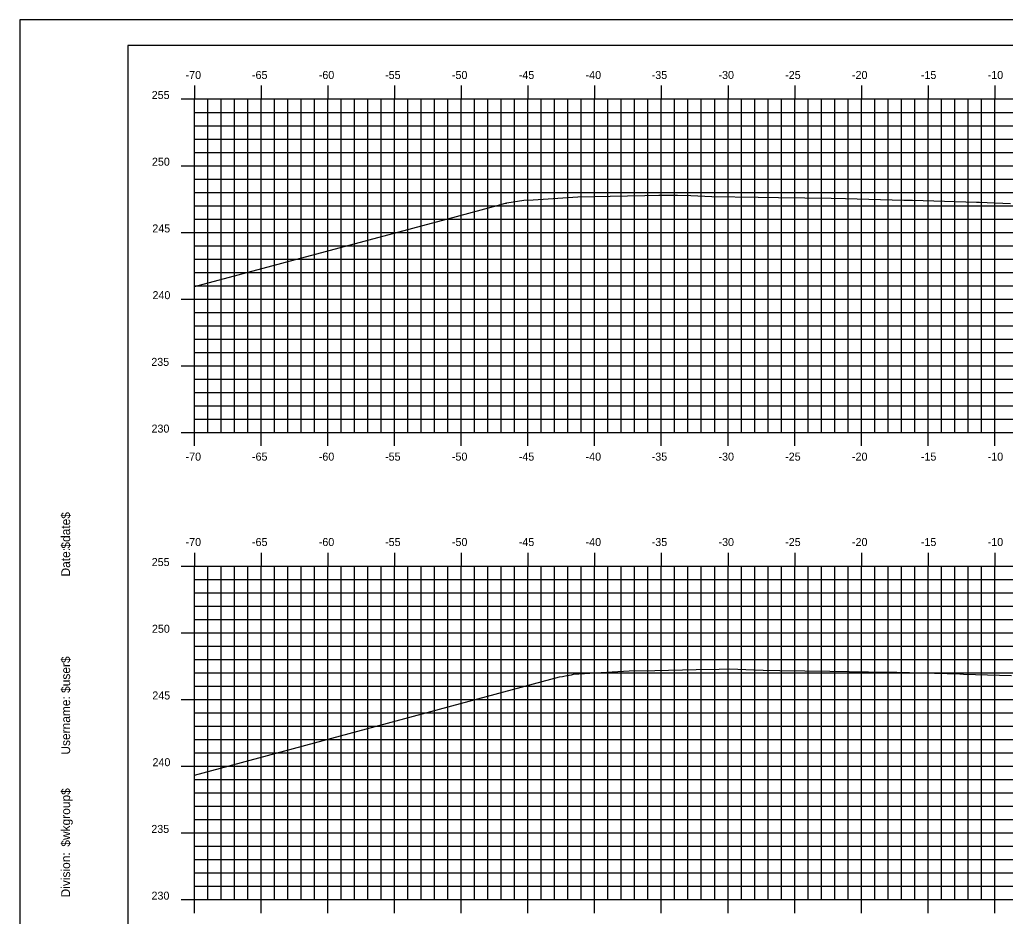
# Model space of a CAD drawing. Extents: x 1170543 to 1177585, y 609599 to 610623.
# Drawn here: x 1171725.9 to 1171799.7, y 609641.6 to 609708.8 of the extents above; entities that cross this region are included whole.
import ezdxf

# ---------------------------------------------------------------- set-up
doc = ezdxf.new("R2010")
doc.units = 0
for name, color, linetype in [('BORDER', 7, 'Continuous'), ('H_V ANNOTATION', 7, 'Continuous'), ('MAJOR', 7, 'Continuous'), ('MINOR', 7, 'Continuous'), ('PLOT BOUNDARY', 7, 'Continuous'), ('S_Roadway_Centerline', 7, 'Continuous')]:
    doc.layers.add(name, color=color, linetype=linetype)

msp = doc.modelspace()

# ---------------------------------------------------------------- linework, layer by layer
at = {"layer": 'BORDER'}
for p, q in [((1171893.965, 609706.872), (1171733.965, 609706.872)), ((1171733.965, 609706.872), (1171733.965, 609601.872))]:
    msp.add_line(p, q, dxfattribs=at)
at = {"layer": 'MAJOR'}
for p, q in [((1171738.965, 609703.874), (1171738.965, 609702.872)), ((1171743.965, 609703.874), (1171743.965, 609702.872)), ((1171748.965, 609703.874), (1171748.965, 609702.872)), ((1171753.965, 609703.874), (1171753.965, 609702.872)), ((1171758.965, 609703.874), (1171758.965, 609702.872)), ((1171763.965, 609703.874), (1171763.965, 609702.872)), ((1171768.965, 609703.874), (1171768.965, 609702.872)), ((1171773.965, 609703.874), (1171773.965, 609702.872)), ((1171778.965, 609703.874), (1171778.965, 609702.872)), ((1171783.965, 609703.874), (1171783.965, 609702.872)), ((1171788.965, 609703.874), (1171788.965, 609702.872)), ((1171793.965, 609703.874), (1171793.965, 609702.872)), ((1171798.965, 609703.874), (1171798.965, 609702.872)), ((1171737.963, 609702.872), (1171738.965, 609702.872)), ((1171738.965, 609702.872), (1171878.965, 609702.872)), ((1171738.965, 609677.872), (1171738.965, 609702.872)), ((1171738.965, 609677.872), (1171738.965, 609702.872)), ((1171738.965, 609702.872), (1171878.965, 609702.872)), ((1171743.965, 609677.872), (1171743.965, 609702.872)), ((1171748.965, 609677.872), (1171748.965, 609702.872)), ((1171753.965, 609677.872), (1171753.965, 609702.872)), ((1171758.965, 609677.872), (1171758.965, 609702.872)), ((1171763.965, 609677.872), (1171763.965, 609702.872)), ((1171768.965, 609677.872), (1171768.965, 609702.872)), ((1171773.965, 609677.872), (1171773.965, 609702.872)), ((1171778.965, 609677.872), (1171778.965, 609702.872)), ((1171783.965, 609677.872), (1171783.965, 609702.872)), ((1171788.965, 609677.872), (1171788.965, 609702.872)), ((1171793.965, 609677.872), (1171793.965, 609702.872)), ((1171798.965, 609677.872), (1171798.965, 609702.872)), ((1171737.963, 609697.872), (1171738.965, 609697.872)), ((1171738.965, 609697.872), (1171878.965, 609697.872)), ((1171737.963, 609692.872), (1171738.965, 609692.872)), ((1171738.965, 609692.872), (1171878.965, 609692.872)), ((1171737.963, 609687.872), (1171738.965, 609687.872)), ((1171738.965, 609687.872), (1171878.965, 609687.872)), ((1171737.963, 609682.872), (1171738.965, 609682.872)), ((1171738.965, 609682.872), (1171878.965, 609682.872)), ((1171737.963, 609677.872), (1171738.965, 609677.872)), ((1171738.965, 609677.872), (1171878.965, 609677.872)), ((1171738.965, 609677.872), (1171878.965, 609677.872)), ((1171738.965, 609676.87), (1171738.965, 609677.872)), ((1171743.965, 609676.87), (1171743.965, 609677.872)), ((1171748.965, 609676.87), (1171748.965, 609677.872)), ((1171753.965, 609676.87), (1171753.965, 609677.872)), ((1171758.965, 609676.87), (1171758.965, 609677.872)), ((1171763.965, 609676.87), (1171763.965, 609677.872)), ((1171768.965, 609676.87), (1171768.965, 609677.872)), ((1171773.965, 609676.87), (1171773.965, 609677.872)), ((1171778.965, 609676.87), (1171778.965, 609677.872)), ((1171783.965, 609676.87), (1171783.965, 609677.872)), ((1171788.965, 609676.87), (1171788.965, 609677.872)), ((1171793.965, 609676.87), (1171793.965, 609677.872)), ((1171798.965, 609676.87), (1171798.965, 609677.872)), ((1171738.965, 609668.874), (1171738.965, 609667.872)), ((1171743.965, 609668.874), (1171743.965, 609667.872)), ((1171748.965, 609668.874), (1171748.965, 609667.872)), ((1171753.965, 609668.874), (1171753.965, 609667.872)), ((1171758.965, 609668.874), (1171758.965, 609667.872)), ((1171763.965, 609668.874), (1171763.965, 609667.872)), ((1171768.965, 609668.874), (1171768.965, 609667.872)), ((1171773.965, 609668.874), (1171773.965, 609667.872)), ((1171778.965, 609668.874), (1171778.965, 609667.872)), ((1171783.965, 609668.874), (1171783.965, 609667.872)), ((1171788.965, 609668.874), (1171788.965, 609667.872)), ((1171793.965, 609668.874), (1171793.965, 609667.872)), ((1171798.965, 609668.874), (1171798.965, 609667.872)), ((1171737.963, 609667.872), (1171738.965, 609667.872)), ((1171738.965, 609667.872), (1171878.965, 609667.872)), ((1171738.965, 609642.872), (1171738.965, 609667.872)), ((1171738.965, 609642.872), (1171738.965, 609667.872)), ((1171738.965, 609667.872), (1171878.965, 609667.872)), ((1171743.965, 609642.872), (1171743.965, 609667.872)), ((1171748.965, 609642.872), (1171748.965, 609667.872)), ((1171753.965, 609642.872), (1171753.965, 609667.872)), ((1171758.965, 609642.872), (1171758.965, 609667.872)), ((1171763.965, 609642.872), (1171763.965, 609667.872)), ((1171768.965, 609642.872), (1171768.965, 609667.872)), ((1171773.965, 609642.872), (1171773.965, 609667.872)), ((1171778.965, 609642.872), (1171778.965, 609667.872)), ((1171783.965, 609642.872), (1171783.965, 609667.872)), ((1171788.965, 609642.872), (1171788.965, 609667.872)), ((1171793.965, 609642.872), (1171793.965, 609667.872)), ((1171798.965, 609642.872), (1171798.965, 609667.872)), ((1171737.963, 609662.872), (1171738.965, 609662.872)), ((1171738.965, 609662.872), (1171878.965, 609662.872)), ((1171737.963, 609657.872), (1171738.965, 609657.872)), ((1171738.965, 609657.872), (1171878.965, 609657.872)), ((1171737.963, 609652.872), (1171738.965, 609652.872)), ((1171738.965, 609652.872), (1171878.965, 609652.872)), ((1171737.963, 609647.872), (1171738.965, 609647.872)), ((1171738.965, 609647.872), (1171878.965, 609647.872)), ((1171737.963, 609642.872), (1171738.965, 609642.872)), ((1171738.965, 609642.872), (1171878.965, 609642.872)), ((1171738.965, 609642.872), (1171878.965, 609642.872)), ((1171738.965, 609641.87), (1171738.965, 609642.872)), ((1171743.965, 609641.87), (1171743.965, 609642.872)), ((1171748.965, 609641.87), (1171748.965, 609642.872)), ((1171753.965, 609641.87), (1171753.965, 609642.872)), ((1171758.965, 609641.87), (1171758.965, 609642.872)), ((1171763.965, 609641.87), (1171763.965, 609642.872)), ((1171768.965, 609641.87), (1171768.965, 609642.872)), ((1171773.965, 609641.87), (1171773.965, 609642.872)), ((1171778.965, 609641.87), (1171778.965, 609642.872)), ((1171783.965, 609641.87), (1171783.965, 609642.872)), ((1171788.965, 609641.87), (1171788.965, 609642.872)), ((1171793.965, 609641.87), (1171793.965, 609642.872)), ((1171798.965, 609641.87), (1171798.965, 609642.872))]:
    msp.add_line(p, q, dxfattribs=at)
at = {"layer": 'MINOR'}
for p, q in [((1171739.965, 609677.872), (1171739.965, 609702.872)), ((1171740.965, 609677.872), (1171740.965, 609702.872)), ((1171741.965, 609677.872), (1171741.965, 609702.872)), ((1171742.965, 609677.872), (1171742.965, 609702.872)), ((1171744.965, 609677.872), (1171744.965, 609702.872)), ((1171745.965, 609677.872), (1171745.965, 609702.872)), ((1171746.965, 609677.872), (1171746.965, 609702.872)), ((1171747.965, 609677.872), (1171747.965, 609702.872)), ((1171749.965, 609677.872), (1171749.965, 609702.872)), ((1171750.965, 609677.872), (1171750.965, 609702.872)), ((1171751.965, 609677.872), (1171751.965, 609702.872)), ((1171752.965, 609677.872), (1171752.965, 609702.872)), ((1171754.965, 609677.872), (1171754.965, 609702.872)), ((1171755.965, 609677.872), (1171755.965, 609702.872)), ((1171756.965, 609677.872), (1171756.965, 609702.872)), ((1171757.965, 609677.872), (1171757.965, 609702.872)), ((1171759.965, 609677.872), (1171759.965, 609702.872)), ((1171760.965, 609677.872), (1171760.965, 609702.872)), ((1171761.965, 609677.872), (1171761.965, 609702.872)), ((1171762.965, 609677.872), (1171762.965, 609702.872)), ((1171764.965, 609677.872), (1171764.965, 609702.872)), ((1171765.965, 609677.872), (1171765.965, 609702.872)), ((1171766.965, 609677.872), (1171766.965, 609702.872)), ((1171767.965, 609677.872), (1171767.965, 609702.872)), ((1171769.965, 609677.872), (1171769.965, 609702.872)), ((1171770.965, 609677.872), (1171770.965, 609702.872)), ((1171771.965, 609677.872), (1171771.965, 609702.872)), ((1171772.965, 609677.872), (1171772.965, 609702.872)), ((1171774.965, 609677.872), (1171774.965, 609702.872)), ((1171775.965, 609677.872), (1171775.965, 609702.872)), ((1171776.965, 609677.872), (1171776.965, 609702.872)), ((1171777.965, 609677.872), (1171777.965, 609702.872)), ((1171779.965, 609677.872), (1171779.965, 609702.872)), ((1171780.965, 609677.872), (1171780.965, 609702.872)), ((1171781.965, 609677.872), (1171781.965, 609702.872)), ((1171782.965, 609677.872), (1171782.965, 609702.872)), ((1171784.965, 609677.872), (1171784.965, 609702.872)), ((1171785.965, 609677.872), (1171785.965, 609702.872)), ((1171786.965, 609677.872), (1171786.965, 609702.872)), ((1171787.965, 609677.872), (1171787.965, 609702.872)), ((1171789.965, 609677.872), (1171789.965, 609702.872)), ((1171790.965, 609677.872), (1171790.965, 609702.872)), ((1171791.965, 609677.872), (1171791.965, 609702.872)), ((1171792.965, 609677.872), (1171792.965, 609702.872)), ((1171794.965, 609677.872), (1171794.965, 609702.872)), ((1171795.965, 609677.872), (1171795.965, 609702.872)), ((1171796.965, 609677.872), (1171796.965, 609702.872)), ((1171797.965, 609677.872), (1171797.965, 609702.872)), ((1171738.965, 609701.872), (1171878.965, 609701.872)), ((1171738.965, 609701.872), (1171739.967, 609701.872)), ((1171738.965, 609700.872), (1171878.965, 609700.872)), ((1171738.965, 609700.872), (1171739.967, 609700.872)), ((1171738.965, 609699.872), (1171878.965, 609699.872)), ((1171738.965, 609699.872), (1171739.967, 609699.872)), ((1171738.965, 609698.872), (1171878.965, 609698.872)), ((1171738.965, 609698.872), (1171739.967, 609698.872)), ((1171738.965, 609696.872), (1171878.965, 609696.872)), ((1171738.965, 609696.872), (1171739.967, 609696.872)), ((1171738.965, 609695.872), (1171878.965, 609695.872)), ((1171738.965, 609695.872), (1171739.967, 609695.872)), ((1171738.965, 609694.872), (1171878.965, 609694.872)), ((1171738.965, 609694.872), (1171739.967, 609694.872)), ((1171738.965, 609693.872), (1171878.965, 609693.872)), ((1171738.965, 609693.872), (1171739.967, 609693.872)), ((1171738.965, 609691.872), (1171878.965, 609691.872)), ((1171738.965, 609691.872), (1171739.967, 609691.872)), ((1171738.965, 609690.872), (1171878.965, 609690.872)), ((1171738.965, 609690.872), (1171739.967, 609690.872)), ((1171738.965, 609689.872), (1171878.965, 609689.872)), ((1171738.965, 609689.872), (1171739.967, 609689.872)), ((1171738.965, 609688.872), (1171878.965, 609688.872)), ((1171738.965, 609688.872), (1171739.967, 609688.872)), ((1171738.965, 609686.872), (1171878.965, 609686.872)), ((1171738.965, 609686.872), (1171739.967, 609686.872)), ((1171738.965, 609685.872), (1171878.965, 609685.872)), ((1171738.965, 609685.872), (1171739.967, 609685.872)), ((1171738.965, 609684.872), (1171878.965, 609684.872)), ((1171738.965, 609684.872), (1171739.967, 609684.872)), ((1171738.965, 609683.872), (1171878.965, 609683.872)), ((1171738.965, 609683.872), (1171739.967, 609683.872)), ((1171738.965, 609681.872), (1171878.965, 609681.872)), ((1171738.965, 609681.872), (1171739.967, 609681.872)), ((1171738.965, 609680.872), (1171878.965, 609680.872)), ((1171738.965, 609680.872), (1171739.967, 609680.872)), ((1171738.965, 609679.872), (1171878.965, 609679.872)), ((1171738.965, 609679.872), (1171739.967, 609679.872)), ((1171738.965, 609678.872), (1171878.965, 609678.872)), ((1171738.965, 609678.872), (1171739.967, 609678.872)), ((1171739.965, 609642.872), (1171739.965, 609667.872)), ((1171740.965, 609642.872), (1171740.965, 609667.872)), ((1171741.965, 609642.872), (1171741.965, 609667.872)), ((1171742.965, 609642.872), (1171742.965, 609667.872)), ((1171744.965, 609642.872), (1171744.965, 609667.872)), ((1171745.965, 609642.872), (1171745.965, 609667.872)), ((1171746.965, 609642.872), (1171746.965, 609667.872)), ((1171747.965, 609642.872), (1171747.965, 609667.872)), ((1171749.965, 609642.872), (1171749.965, 609667.872)), ((1171750.965, 609642.872), (1171750.965, 609667.872)), ((1171751.965, 609642.872), (1171751.965, 609667.872)), ((1171752.965, 609642.872), (1171752.965, 609667.872)), ((1171754.965, 609642.872), (1171754.965, 609667.872)), ((1171755.965, 609642.872), (1171755.965, 609667.872)), ((1171756.965, 609642.872), (1171756.965, 609667.872)), ((1171757.965, 609642.872), (1171757.965, 609667.872)), ((1171759.965, 609642.872), (1171759.965, 609667.872)), ((1171760.965, 609642.872), (1171760.965, 609667.872)), ((1171761.965, 609642.872), (1171761.965, 609667.872)), ((1171762.965, 609642.872), (1171762.965, 609667.872)), ((1171764.965, 609642.872), (1171764.965, 609667.872)), ((1171765.965, 609642.872), (1171765.965, 609667.872)), ((1171766.965, 609642.872), (1171766.965, 609667.872)), ((1171767.965, 609642.872), (1171767.965, 609667.872)), ((1171769.965, 609642.872), (1171769.965, 609667.872)), ((1171770.965, 609642.872), (1171770.965, 609667.872)), ((1171771.965, 609642.872), (1171771.965, 609667.872)), ((1171772.965, 609642.872), (1171772.965, 609667.872)), ((1171774.965, 609642.872), (1171774.965, 609667.872)), ((1171775.965, 609642.872), (1171775.965, 609667.872)), ((1171776.965, 609642.872), (1171776.965, 609667.872)), ((1171777.965, 609642.872), (1171777.965, 609667.872)), ((1171779.965, 609642.872), (1171779.965, 609667.872)), ((1171780.965, 609642.872), (1171780.965, 609667.872)), ((1171781.965, 609642.872), (1171781.965, 609667.872)), ((1171782.965, 609642.872), (1171782.965, 609667.872)), ((1171784.965, 609642.872), (1171784.965, 609667.872)), ((1171785.965, 609642.872), (1171785.965, 609667.872)), ((1171786.965, 609642.872), (1171786.965, 609667.872)), ((1171787.965, 609642.872), (1171787.965, 609667.872)), ((1171789.965, 609642.872), (1171789.965, 609667.872)), ((1171790.965, 609642.872), (1171790.965, 609667.872)), ((1171791.965, 609642.872), (1171791.965, 609667.872)), ((1171792.965, 609642.872), (1171792.965, 609667.872)), ((1171794.965, 609642.872), (1171794.965, 609667.872)), ((1171795.965, 609642.872), (1171795.965, 609667.872)), ((1171796.965, 609642.872), (1171796.965, 609667.872)), ((1171797.965, 609642.872), (1171797.965, 609667.872)), ((1171738.965, 609666.872), (1171878.965, 609666.872)), ((1171738.965, 609666.872), (1171739.967, 609666.872)), ((1171738.965, 609665.872), (1171878.965, 609665.872)), ((1171738.965, 609665.872), (1171739.967, 609665.872)), ((1171738.965, 609664.872), (1171878.965, 609664.872)), ((1171738.965, 609664.872), (1171739.967, 609664.872)), ((1171738.965, 609663.872), (1171878.965, 609663.872)), ((1171738.965, 609663.872), (1171739.967, 609663.872)), ((1171738.965, 609661.872), (1171878.965, 609661.872)), ((1171738.965, 609661.872), (1171739.967, 609661.872)), ((1171738.965, 609660.872), (1171878.965, 609660.872)), ((1171738.965, 609660.872), (1171739.967, 609660.872)), ((1171738.965, 609659.872), (1171878.965, 609659.872)), ((1171738.965, 609659.872), (1171739.967, 609659.872)), ((1171738.965, 609658.872), (1171878.965, 609658.872)), ((1171738.965, 609658.872), (1171739.967, 609658.872)), ((1171738.965, 609656.872), (1171878.965, 609656.872)), ((1171738.965, 609656.872), (1171739.967, 609656.872)), ((1171738.965, 609655.872), (1171878.965, 609655.872)), ((1171738.965, 609655.872), (1171739.967, 609655.872)), ((1171738.965, 609654.872), (1171878.965, 609654.872)), ((1171738.965, 609654.872), (1171739.967, 609654.872)), ((1171738.965, 609653.872), (1171878.965, 609653.872)), ((1171738.965, 609653.872), (1171739.967, 609653.872)), ((1171738.965, 609651.872), (1171878.965, 609651.872)), ((1171738.965, 609651.872), (1171739.967, 609651.872)), ((1171738.965, 609650.872), (1171878.965, 609650.872)), ((1171738.965, 609650.872), (1171739.967, 609650.872)), ((1171738.965, 609649.872), (1171878.965, 609649.872)), ((1171738.965, 609649.872), (1171739.967, 609649.872)), ((1171738.965, 609648.872), (1171878.965, 609648.872)), ((1171738.965, 609648.872), (1171739.967, 609648.872)), ((1171738.965, 609646.872), (1171878.965, 609646.872)), ((1171738.965, 609646.872), (1171739.967, 609646.872)), ((1171738.965, 609645.872), (1171878.965, 609645.872)), ((1171738.965, 609645.872), (1171739.967, 609645.872)), ((1171738.965, 609644.872), (1171878.965, 609644.872)), ((1171738.965, 609644.872), (1171739.967, 609644.872)), ((1171738.965, 609643.872), (1171878.965, 609643.872)), ((1171738.965, 609643.872), (1171739.967, 609643.872))]:
    msp.add_line(p, q, dxfattribs=at)
at = {"layer": 'PLOT BOUNDARY'}
msp.add_lwpolyline([(1171725.872, 609598.813), (1171895.872, 609598.813), (1171895.872, 609708.813), (1171725.872, 609708.813)], close=True, dxfattribs=at)
at = {"layer": 'S_Roadway_Centerline'}
for points in [[(1171738.965, 609688.816), (1171758.622, 609694.07), (1171761.651, 609694.896), (1171762.28, 609695.065), (1171762.313, 609695.07), (1171762.32, 609695.071), (1171762.351, 609695.075), (1171762.376, 609695.08), (1171763.654, 609695.28), (1171764.369, 609695.323), (1171767.711, 609695.53), (1171770.138, 609695.583), (1171772.727, 609695.642), (1171773.771, 609695.654), (1171775.19, 609695.672), (1171776.182, 609695.635), (1171777.744, 609695.577), (1171781.228, 609695.524), (1171782.76, 609695.5), (1171786.686, 609695.433), (1171787.776, 609695.415), (1171792.144, 609695.296), (1171792.792, 609695.279), (1171797.603, 609695.147), (1171797.809, 609695.141), (1171800.141, 609695.049)], [(1171738.965, 609652.21), (1171766.345, 609659.562), (1171766.562, 609659.597), (1171766.658, 609659.622), (1171766.888, 609659.658), (1171767.226, 609659.729), (1171767.39, 609659.762), (1171768.609, 609659.834), (1171771.563, 609660.012), (1171773.489, 609660.056), (1171776.575, 609660.124), (1171778.309, 609660.147), (1171779.112, 609660.157), (1171780.904, 609660.088), (1171781.588, 609660.063), (1171782.843, 609660.045), (1171786.601, 609659.995), (1171790.944, 609659.921), (1171791.614, 609659.909), (1171796.347, 609659.784), (1171796.627, 609659.776), (1171800.213, 609659.677)]]:
    msp.add_lwpolyline(points, dxfattribs=at)

# ---------------------------------------------------------------- texts
at = {"layer": 'BORDER'}
for s, p in [('$date$', (1171729.65, 609669.177)), ('Date:', (1171729.65, 609667.089)), ('$user$', (1171729.65, 609658.364)), ('Username:', (1171729.65, 609653.74)), ('$wkgroup$', (1171729.65, 609646.842)), ('Division:', (1171729.65, 609643.038))]:
    msp.add_text(s, height=0.6696, rotation=90, dxfattribs=at).set_placement(p)
at = {"layer": 'H_V ANNOTATION'}
for s, p in [('-70', (1171738.306, 609704.372)), ('-65', (1171743.283, 609704.372)), ('-60', (1171748.291, 609704.372)), ('-55', (1171753.261, 609704.372)), ('-50', (1171758.269, 609704.372)), ('-45', (1171763.283, 609704.372)), ('-40', (1171768.291, 609704.372)), ('-35', (1171773.245, 609704.372)), ('-30', (1171778.253, 609704.372)), ('-25', (1171783.25, 609704.372)), ('-20', (1171788.258, 609704.372)), ('-15', (1171793.422, 609704.372)), ('-10', (1171798.43, 609704.372)), ('255', (1171735.768, 609702.872)), ('250', (1171735.784, 609697.872)), ('245', (1171735.811, 609692.872)), ('240', (1171735.827, 609687.872)), ('235', (1171735.736, 609682.872)), ('230', (1171735.752, 609677.872)), ('-70', (1171738.306, 609675.772)), ('-65', (1171743.283, 609675.772)), ('-60', (1171748.291, 609675.772)), ('-55', (1171753.261, 609675.772)), ('-50', (1171758.269, 609675.772)), ('-45', (1171763.283, 609675.772)), ('-40', (1171768.291, 609675.772)), ('-35', (1171773.245, 609675.772)), ('-30', (1171778.253, 609675.772)), ('-25', (1171783.25, 609675.772)), ('-20', (1171788.258, 609675.772)), ('-15', (1171793.422, 609675.772)), ('-10', (1171798.43, 609675.772)), ('-70', (1171738.306, 609669.372)), ('-65', (1171743.283, 609669.372)), ('-60', (1171748.291, 609669.372)), ('-55', (1171753.261, 609669.372)), ('-50', (1171758.269, 609669.372)), ('-45', (1171763.283, 609669.372)), ('-40', (1171768.291, 609669.372)), ('-35', (1171773.245, 609669.372)), ('-30', (1171778.253, 609669.372)), ('-25', (1171783.25, 609669.372)), ('-20', (1171788.258, 609669.372)), ('-15', (1171793.422, 609669.372)), ('-10', (1171798.43, 609669.372)), ('255', (1171735.768, 609667.872)), ('250', (1171735.784, 609662.872)), ('245', (1171735.811, 609657.872)), ('240', (1171735.827, 609652.872)), ('235', (1171735.736, 609647.872)), ('230', (1171735.752, 609642.872))]:
    msp.add_text(s, height=0.6, dxfattribs=at).set_placement(p)

doc.saveas('drawing.dxf')
